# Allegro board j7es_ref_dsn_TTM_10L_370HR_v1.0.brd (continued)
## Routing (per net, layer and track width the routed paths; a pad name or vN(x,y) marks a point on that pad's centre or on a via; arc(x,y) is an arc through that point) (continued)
LPDDR4_CK_T: length 33.6
  TOP w0.229: U11.J8 v1(126.13,64.51) ; U11.P8 v1(126.13,68.41) ; v1(110.25,65.75) 110.25,65.75 U9.H1
  L2-SIGNAL w0.14: v1(126.13,68.41) 126.71,67.83 126.71,67.31 126.35,66.96 v1(126.35,66.56) 126.35,66.09 126.47,65.98 126.47,64.84 v1(126.13,64.51)
  L7-SIGNAL w0.163: v1(126.35,66.56) 126.35,66.03 125.92,65.6 121.7,65.6 120.99,64.89 120.15,64.89 119.99,64.72 119.99,64.06 119.99,63.78 119.62,63.41 119.24,63.41 118.97,63.41 118.59,63.79 118.59,64.81 118.46,64.94 118.07,64.94 117.86,64.72 117.86,64.08 117.86,63.81 117.43,63.38 117.05,63.38 116.78,63.38 116.46,63.7 116.46,64.75 116.31,64.89 116.06,64.89 115.87,64.71 115.87,64.03 115.88,63.75 115.51,63.39 115,63.39 114.72,63.39 114.4,63.71 114.4,64.78 114.21,64.96 113.93,64.96 113.72,64.75 113.72,63.89 113.3,63.47 112.59,63.47 112.24,63.81 112.24,65.58 112.08,65.75 v1(110.25,65.75)
LPDDR4_CKE0: length 33.4
  TOP w0.33: U11.P4 129.11,68.26 129.12,68.26 129.27,68.41 v1(129.33,68.41) ; U9.G3 v1(108.65,64.95) ; U11.J4 v1(129.33,64.51)
  L2-SIGNAL w0.142: v1(129.33,68.41) 129.3,68.41 128.92,68.03 128.92,67.59 128.68,67.35 128.68,66.83 v1(128.92,66.56) 128.92,64.87 129.29,64.51 v1(129.33,64.51)
  L9-SIGNAL w0.142: v1(128.92,66.56) 128.92,66.2 128.67,65.95 128.06,65.95 127.94,65.84 127.94,65.44 127.82,65.31 127.56,65.31 127.45,65.43 127.45,65.99 127.34,66.11 126.78,66.11 125.72,66.11 121.79,66.11 120.01,64.33 116.18,64.33 116.03,64.48 116.03,65.42 115.93,65.52 115.34,65.52 115.14,65.32 115.14,64.47 114.99,64.33 114.43,64.33 114.29,64.47 114.29,65.5 114.14,65.65 113.51,65.65 113.36,65.5 113.36,64.94 113.21,64.79 112.82,64.79 112.68,64.93 112.68,65.31 112.34,65.65 111.28,65.65 110.97,65.34 109.05,65.34 v1(108.65,64.95)
LPDDR4_CKE1: length 33.4
  TOP w0.33: U11.P5 128.13,68.08 v1(127.73,68.41) ; U9.J3 v1(108.65,66.55) ; U11.J5 v1(127.73,64.51)
  L2-SIGNAL w0.142: v1(127.73,68.41) 127.74,68.41 128.13,68.01 128.13,67.59 127.86,67.32 127.86,66.83 v1(128.13,66.56) 128.13,65.33 128.13,65.32 128.13,64.86 127.77,64.51 v1(127.73,64.51)
  L9-SIGNAL w0.142: v1(128.13,66.56) 126.95,66.56 126.52,67 121.46,67 120.61,66.14 117.47,66.14 117.32,65.99 117.32,65.67 117.47,65.52 119.84,65.52 119.96,65.39 119.96,65.12 119.75,64.91 116.89,64.91 116.66,65.14 116.66,65.99 116.5,66.15 109.05,66.15 v1(108.65,66.55)
LPDDR4_CSN0_0: length 28.4
  TOP w0.33: U11.H4 v1(128.53,64.51) ; U9.J5 v1(107.05,66.55)
  L9-SIGNAL w0.142: v1(128.53,64.51) 128.12,64.91 127.56,64.91 127.13,64.49 126.92,64.49 125.7,65.7 122.07,65.7 120.24,63.87 114.17,63.87 113.76,64.28 113.21,64.28 113.03,64.1 113.03,63.11 112.83,62.91 112.53,62.91 112.32,63.11 112.32,64.35 111.96,64.71 110.74,64.71 110.58,64.55 108.42,64.55 108.25,64.71 108.25,65.11 108.02,65.34 108.01,65.34 107.67,65.34 107.45,65.56 107.45,66.15 v1(107.05,66.55)
LPDDR4_CSN0_1: length 28.2
  TOP w0.33: U11.R4 v1(128.53,68.41) ; U9.K3 v1(108.65,67.35)
  L9-SIGNAL w0.142: v1(128.53,68.41) 128.12,68.81 128.12,69.87 128.12,69.88 128.12,70.65 127.87,70.9 127.4,70.9 126.42,69.92 124.86,69.92 124.85,69.92 120.9,69.92 120.55,69.56 120.55,68.62 120.19,68.27 119.63,68.27 119.28,68.62 119.28,69.59 119.1,69.76 117.02,69.76 116.76,69.51 116.76,67.68 116.54,67.45 114.78,67.45 114.49,67.75 109.06,67.75 v1(108.65,67.35)
LPDDR4_CSN1_0: length 28.4
  TOP w0.33: U11.H3 v1(129.33,63.86) ; v1(107.05,64.95) 106.65,65.35 U9.G5
  L9-SIGNAL w0.142: v1(129.33,63.86) 128.93,63.46 128.93,62.36 128.71,62.14 128.35,62.14 128.12,62.37 128.12,62.85 127.31,63.66 126.54,63.66 126.29,63.41 114.02,63.41 113.79,63.19 113.79,62.65 113.56,62.42 111.94,62.42 111.72,62.64 111.72,63.5 111.48,63.75 107.62,63.75 107.46,63.91 107.46,64.54 v1(107.05,64.95)
LPDDR4_CSN1_1: length 28.3
  TOP w0.33: U9.J2 109.05,66.94 v1(109.45,66.55) ; v1(130.13,69.06) 129.73,68.73 U11.R3
  L9-SIGNAL w0.142: v1(130.13,69.06) 129.72,69.47 129.72,69.54 129.73,69.54 129.73,70.01 129.57,70.17 129.08,70.17 128.93,70.02 128.93,67.6 128.93,67.6 128.93,67.59 128.69,67.36 128.69,67.36 128.66,67.34 127.82,67.34 126.68,68.48 126.68,69.25 126.47,69.46 121.4,69.46 121.06,69.11 121.06,68.05 119.95,66.94 109.85,66.94 v1(109.45,66.55)
LPDDR4_DM0_DBI0#: length 31.4
  TOP w0.33: v1(130.13,61.26) 130.13,61.26 U11.C3 ; U9.A3 v1(108.65,60.15)
  L4-SIGNAL w0.163: v1(130.13,61.26) 129.87,61 129.5,61 129.49,61 129.16,61 128.93,60.77 128.93,59.8 128.93,59.8 128.93,59.79 128.64,59.5 126.24,59.5 125.58,58.84 125.4,58.84 124.64,58.84 124.18,58.38 121.78,58.38 121.42,58.03 119.65,58.03 119.51,58.18 119.51,58.66 119.66,58.82 121.26,58.82 121.41,58.97 121.41,59.25 121.23,59.43 116.23,59.43 115.9,59.76 115.9,60.34 115.75,60.49 115.42,60.49 115.27,60.34 115.27,60.01 115.11,59.86 114.83,59.86 114.12,60.57 111.28,60.57 110.39,59.68 109.06,59.68 108.65,60.09 v1(108.65,60.15)
LPDDR4_DM1_DBI1#: length 25.5
  TOP w0.33: U11.C10 v1(124.53,60.61) ; U9.E4 v1(107.85,63.35)
  L2-SIGNAL w0.142: v1(124.53,60.61) 124.13,60.21 124.13,59.88 123.14,58.89 116.83,58.89 116.41,59.31 115.41,59.31 115.26,59.46 115.26,60.37 115.11,60.52 114.88,60.52 114.73,60.37 114.73,59.98 114.57,59.83 114.33,59.83 114.17,59.98 114.17,60.34 113.96,60.55 113.68,60.55 113.53,60.4 113.53,60.29 113.38,60.14 113.15,60.14 113,60.29 113,60.4 112.84,60.55 112.62,60.55 112.46,60.4 112.46,60.29 112.31,60.14 112.08,60.14 111.93,60.29 111.93,60.4 111.78,60.55 111.55,60.55 111.4,60.4 111.4,60.29 111.24,60.14 111.02,60.14 110.86,60.29 110.86,60.39 110.71,60.54 107.66,60.54 107.45,60.75 107.45,62.94 v1(107.85,63.35)
LPDDR4_DM2_DBI2#: length 31.5
  TOP w0.33: v1(130.13,71.66) 130.13,71.66 U11.Y3 ; v1(110.25,69.75) 110.25,69.75 U9.N1
  L4-SIGNAL w0.163: v1(110.25,69.75) 110.3,69.75 110.36,69.8 110.72,69.8 111.14,69.38 112.01,69.38 112.16,69.23 112.63,69.23 113.04,69.64 113.04,70.13 113.74,70.83 113.74,71.77 113.89,71.92 117.14,71.92 117.3,72.08 117.3,72.3 117.14,72.46 115.21,72.46 115.05,72.62 115.05,72.83 115.21,72.99 117.63,72.99 117.83,72.79 117.83,72.1 118.06,71.87 119.84,71.87 119.99,71.72 119.99,71.26 120,71.25 120,70.34 120.15,70.18 121.35,70.18 122.68,71.51 126.44,71.51 126.75,71.83 128.38,71.83 128.44,71.88 129.9,71.88 v1(130.13,71.66)
LPDDR4_DM3_DBI3#: length 22
  TOP w0.33: v1(123.73,72.31) 123.73,72.31 U11.Y10 ; v1(107.05,71.35) 107.05,71.35 U9.R5
  L2-SIGNAL w0.142: v1(123.73,72.31) 123.56,72.31 123.37,72.51 123.37,73.08 122.72,73.73 122.28,73.73 120.9,75.1 116.84,75.1 116.69,74.94 116.69,74.54 116.54,74.39 114.67,74.39 114.51,74.54 114.51,74.92 114.36,75.07 112.23,75.07 112.2,75.05 112.19,75.05 110.49,73.35 109.28,73.35 108.25,72.32 108.25,71.97 108.03,71.75 107.45,71.75 v1(107.05,71.35)
LPDDR4_DQ0: length 31.4
  TOP w0.33: v1(130.93,59.96) 130.88,59.96 130.55,60.28 U11.B2 ; U9.A5 v1(107.05,60.14)
  L4-SIGNAL w0.163: v1(107.05,60.14) 107.05,59.57 108.41,58.21 109.25,58.21 109.4,58.06 109.4,57.52 109.55,57.37 110.01,57.37 110.16,57.52 110.16,58.08 110.31,58.23 110.72,58.23 110.87,58.08 110.87,56.5 111.25,56.13 113.77,56.13 114.2,56.56 114.49,56.56 124.84,56.56 125.09,56.81 125.09,57.21 125.35,57.47 127.18,57.47 127.79,58.08 129.66,58.08 130.93,59.35 v1(130.93,59.96)
LPDDR4_DQ1: length 31.4
  TOP w0.33: U11.C2 v1(130.93,60.61) ; U9.A6 v1(106.25,60.14)
  L4-SIGNAL w0.163: v1(106.25,60.14) 106.44,59.96 106.44,59.49 110.26,55.67 114.03,55.67 114.45,56.1 127.45,56.1 128.17,56.82 128.17,56.84 128.95,57.62 129.84,57.62 131.37,59.15 131.37,60.17 v1(130.93,60.61)
LPDDR4_DQ2: length 31.4
  TOP w0.33: U11.E2 v1(130.93,61.91) ; U9.B5 v1(107.05,60.95)
  L4-SIGNAL w0.163: v1(130.93,61.91) 130.53,61.51 130.53,59.6 129.54,58.61 126.64,58.61 125.96,57.93 125.02,57.93 124.83,57.74 124.56,57.47 122.16,57.47 121.7,57.01 115.19,57.01 114.71,57.49 114.71,58.54 113.62,59.63 111.67,59.63 111.66,59.63 110.79,58.77 108.59,58.77 107.45,59.9 107.45,60.55 v1(107.05,60.95)
LPDDR4_DQ3: length 31.4
  TOP w0.33: U9.C2 v1(109.45,61.75) ; U11.F2 v1(130.93,63.21)
  L4-SIGNAL w0.163: v1(130.93,63.21) 131.15,63.21 131.32,63.04 131.32,62.46 131.18,62.31 130.94,62.31 130.34,62.92 130.34,63.23 130.22,63.35 129.88,63.35 129.77,63.24 129.77,62.89 129.49,62.61 129.28,62.61 128.54,61.87 127.8,61.87 127.09,62.58 126.72,62.58 126.26,63.03 120.07,63.03 119.52,63.58 118.7,63.58 118.49,63.78 117.78,63.78 117.62,63.93 117.62,64.4 117.47,64.55 117.24,64.55 117.09,64.4 117.09,63.93 116.94,63.78 116.55,63.78 116.39,63.93 116.39,64.48 116.24,64.63 116.01,64.63 115.86,64.48 115.86,63.93 115.71,63.78 115.48,63.78 115.33,63.93 115.33,64.48 115.17,64.63 114.94,64.63 114.79,64.48 114.79,63.93 114.64,63.78 111.97,63.78 111.48,63.29 111.48,62.56 111.32,62.4 110.77,62.4 110.52,62.15 109.86,62.15 v1(109.45,61.75)
LPDDR4_DQ4: length 31.4
  TOP w0.33: U9.B4 107.45,61.35 v1(107.85,60.95) ; U11.F4 129.33,63.21 v1(129.33,63.21)
  L4-SIGNAL w0.163: v1(107.85,60.95) 108.26,61.35 108.26,64.31 108.49,64.54 110.72,64.54 111.35,65.17 113.69,65.17 114.24,65.73 120.57,65.73 120.88,65.42 120.88,64.25 121.05,64.08 121.37,64.08 121.52,64.23 121.52,65.25 122.02,65.75 126.92,65.75 127.23,66.06 128.51,66.06 128.93,65.64 128.93,63.61 v1(129.33,63.21)
LPDDR4_DQ5: length 31.4
  TOP w0.33: U11.E4 v1(128.53,62.56) ; U9.C3 v1(108.65,61.75)
  L4-SIGNAL w0.163: v1(128.53,62.56) 128.4,62.56 128.13,62.83 128.13,65.46 127.91,65.67 127.35,65.67 126.95,65.28 126.95,63.86 126.48,63.39 122,63.39 121.82,63.57 120.45,63.57 120.29,63.72 120.29,65.12 120.14,65.27 119.65,65.27 119.5,65.12 119.5,64.22 119.35,64.07 118.97,64.07 118.83,64.21 118.82,64.22 118.82,65.04 118.6,65.27 114.63,65.27 114.07,64.71 114,64.71 111.65,64.71 110.68,63.74 109.29,63.74 109.05,63.51 109.05,62.15 v1(108.65,61.75)
LPDDR4_DQ6: length 31.5
  TOP w0.33: v1(128.53,60.61) 128.59,60.61 128.91,60.93 U11.C4 ; U9.A2 v1(109.45,60.15)
  L4-SIGNAL w0.163: v1(128.53,60.61) 127.78,59.86 126.92,59.86 126.77,60.01 126.77,60.47 126.62,60.62 125.89,60.62 125.73,60.46 125.73,59.81 125.73,59.8 125.73,59.79 125.49,59.56 125.48,59.56 125.41,59.49 125.21,59.49 124.43,59.49 124.23,59.49 124.03,59.69 124.03,60.47 123.9,60.59 123.52,60.59 123.37,60.44 123.37,59.25 123.22,59.1 122.63,59.1 122.48,59.24 122.48,59.66 122.21,59.93 119.6,59.93 119.45,60.09 119.45,60.31 119.6,60.47 121.21,60.47 121.36,60.62 121.36,60.85 121.21,61 119.07,61 118.92,60.85 118.92,60.09 118.77,59.93 116.51,59.93 116.36,60.09 116.36,60.87 116.2,61.03 111.09,61.03 110.61,60.54 109.85,60.54 v1(109.45,60.15)
LPDDR4_DQ7: length 31.4
  TOP w0.33: v1(129.33,60.61) 129.33,60.6 128.93,60.28 U11.B4 ; U9.A4 v1(107.85,60.14)
  L4-SIGNAL w0.163: v1(129.33,60.61) 129.61,60.32 129.61,60.32 129.73,60.2 129.73,59.66 129.24,59.17 126.55,59.17 125.77,58.38 125.21,58.38 124.83,58.38 124.37,57.93 121.97,57.93 121.61,57.57 117.01,57.57 116.84,57.74 116.84,58.11 117.02,58.28 118.82,58.28 118.97,58.44 118.97,58.82 118.82,58.97 114.96,58.97 113.82,60.11 111.47,60.11 110.58,59.22 108.78,59.22 v1(107.85,60.14)
LPDDR4_DQ8: length 25.5
  TOP w0.33: U11.B11 v1(122.93,59.96) ; U9.D1 109.85,62.95 v1(110.25,62.55)
  L2-SIGNAL w0.142: v1(122.93,59.96) 123.32,60.44 123.32,60.77 123.09,61 122.77,61 122.74,60.98 122.32,60.98 122.29,61 121.96,61 121.96,61 120.14,61 119.3,61 119.11,61.19 119.11,64.54 118.97,64.68 118.54,64.68 118.43,64.57 118.43,60.9 118.25,60.72 117.88,60.72 117.72,60.88 117.72,62.4 117.57,62.55 116.7,62.55 116.47,62.78 112.24,62.78 112.09,62.63 112.09,62.13 111.92,61.96 111.65,61.96 111.51,62.1 111.51,62.58 111.38,62.7 110.82,62.7 110.66,62.55 v1(110.25,62.55)
LPDDR4_DQ9: length 25.6
  TOP w0.33: U9.C4 v1(107.85,61.75) ; U11.C11 v1(122.93,60.61)
  L2-SIGNAL w0.142: v1(122.93,60.61) 122.23,59.91 120.79,59.91 120.64,60.06 120.64,60.39 120.48,60.54 120.26,60.54 120.1,60.39 120.1,60.06 119.95,59.91 119.72,59.91 119.57,60.06 119.57,60.39 119.42,60.54 119.19,60.54 119.04,60.39 119.04,60.06 118.91,59.93 117.48,59.93 117.26,60.15 117.26,61.41 117.07,61.6 116.85,61.6 116.37,61.12 116.05,61.12 115.85,61.32 115.85,62.2 115.72,62.32 114.88,62.32 114.71,62.14 114.71,61.66 114.55,61.51 114.34,61.51 114.19,61.66 114.19,62.09 114.03,62.24 113.82,62.24 113.65,62.08 113.65,61.63 113.5,61.48 113.27,61.48 113.12,61.63 113.12,62.14 112.95,62.31 112.74,62.31 112.59,62.15 112.59,61.65 112.43,61.49 111.06,61.49 110.65,61.91 110.65,61.91 110.42,62.14 110.41,62.14 110.41,62.15 109.29,62.15 109.06,62.38 109.06,62.39 109.05,62.39 109.05,62.74 108.85,62.94 108.49,62.94 108.26,62.71 108.26,62.38 108.26,62.38 108.26,62.15 v1(107.85,61.75)
LPDDR4_DQ10: length 25.5
  TOP w0.33: U11.E11 122.93,62.56 v1(122.93,62.56) ; U9.F1 v1(110.25,64.15)
  L2-SIGNAL w0.142: v1(110.25,64.15) 110.84,64.15 110.97,64.28 110.97,64.46 111.27,64.76 111.51,64.76 111.66,64.61 111.66,64.17 111.8,64.02 112.12,64.02 112.27,64.18 112.27,64.61 112.42,64.76 112.65,64.76 112.8,64.61 112.8,64.18 112.96,64.02 113.19,64.02 113.34,64.18 113.34,64.61 113.49,64.76 113.72,64.76 113.87,64.61 113.87,64.18 114.02,64.02 114.33,64.02 114.48,64.18 114.48,65.65 114.66,65.83 114.96,65.83 115.11,65.67 115.11,64.13 115.26,63.98 115.59,63.98 115.74,64.13 115.74,65.65 115.92,65.83 119.89,65.83 120.28,65.44 120.28,62.3 120.43,62.14 120.75,62.14 120.91,62.3 121.5,62.3 121.65,62.14 122.08,62.14 122.51,62.14 v1(122.93,62.56)
LPDDR4_DQ11: length 25.6
  TOP w0.33: U11.F11 v1(123.73,62.56) ; U9.G2 109.05,65.35 v1(109.45,64.95)
  L2-SIGNAL w0.142: v1(109.45,64.95) 109.85,64.55 110.42,64.55 111.09,65.22 113.85,65.22 114.01,65.37 114.01,65.6 113.85,65.75 111.46,65.75 111.3,65.9 111.3,66.13 111.45,66.28 112.96,66.28 113.32,66.64 114.09,66.64 114.44,66.28 120.07,66.28 120.74,65.61 120.74,62.88 120.87,62.75 121.58,62.75 121.84,63.01 123.09,63.01 123.26,62.84 123.45,62.84 v1(123.73,62.56)
LPDDR4_DQ12: length 25.5
  TOP w0.33: U9.F2 v1(109.45,64.15) ; U11.F9 v1(124.53,62.56)
  L2-SIGNAL w0.142: v1(109.45,64.15) 109.21,64.15 109.05,64.3 109.05,65.97 109.24,66.15 109.66,66.15 109.85,65.96 109.85,65.91 109.85,65.91 109.85,65.58 109.85,65.58 109.85,65.5 110.01,65.34 110.52,65.34 110.69,65.52 110.69,66.54 111.43,67.27 111.9,67.27 112.05,67.12 112.05,66.92 112.21,66.77 112.73,66.77 112.88,66.92 112.88,67.12 113.03,67.27 114.1,67.27 114.63,66.74 120.27,66.74 121.2,65.81 121.2,63.78 121.4,63.58 121.96,63.58 122.14,63.41 123.12,63.41 123.42,63.1 124.78,63.1 124.93,62.95 124.93,62.67 124.82,62.56 v1(124.53,62.56)
LPDDR4_DQ13: length 25.5
  TOP w0.33: U11.E9 v1(125.33,62.56) ; U9.F3 v1(108.65,64.15)
  L2-SIGNAL w0.142: v1(125.33,62.56) 125.53,62.56 125.76,62.78 125.76,63.23 125.55,63.44 123.57,63.44 123.22,63.79 122.28,63.79 121.65,64.42 121.65,66.03 120.46,67.22 114.82,67.22 114.31,67.73 111.2,67.73 110.42,66.95 108.46,66.95 108.25,66.74 108.25,64.54 v1(108.65,64.15)
LPDDR4_DQ14: length 25.6
  TOP w0.33: U9.D3 108.25,62.95 v1(108.65,62.55) ; v1(125.33,60.61) 125.33,60.61 124.93,60.93 U11.C9
  L2-SIGNAL w0.142: v1(108.65,62.55) 108.65,62.3 108.81,62.14 108.82,62.14 109.05,61.91 109.05,61.59 109.06,61.59 109.06,61.58 109.29,61.35 110.56,61.35 110.9,61.01 115.48,61.01 115.72,60.77 115.72,60.08 116.01,59.79 116.63,59.79 117.07,59.35 122.94,59.35 123.8,60.21 123.8,60.7 124.54,61.43 125.78,61.43 126.05,61.16 126.05,60.54 125.73,60.21 125.73,59.63 125.53,59.43 125.16,59.43 124.93,59.66 124.93,60.21 v1(125.33,60.61)
LPDDR4_DQ15: length 25.5
  TOP w0.33: U9.F5 v1(107.05,64.15) ; U11.B9 v1(124.53,59.96)
  L2-SIGNAL w0.142: v1(107.05,64.15) 106.65,63.75 106.65,59.96 106.93,59.68 113.63,59.68 114.46,58.85 116.23,58.85 116.64,58.44 123.33,58.44 123.42,58.53 124.43,58.53 124.74,58.84 124.74,59.17 124.53,59.38 v1(124.53,59.96)
LPDDR4_DQ16: length 31.6
  TOP w0.33: U9.L5 v1(107.05,68.15) ; U11.AA2 130.53,72.63 v1(130.13,72.96)
  L4-SIGNAL w0.163: v1(130.13,72.96) 130,73.09 129.41,73.09 129.08,73.41 127.55,73.41 127.36,73.61 127.36,73.91 127.35,73.95 127.23,74.07 126.86,74.07 126.71,73.91 126.71,73.22 126.53,73.04 125.89,73.04 125.73,73.2 125.73,74.24 125.5,74.46 112.96,74.46 112.06,73.57 112.06,72.11 111.7,71.75 109.28,71.75 109.05,71.53 109.05,71.16 108.84,70.95 108.47,70.95 108.25,70.73 108.25,70.36 108.04,70.15 107.65,70.15 107.45,69.95 107.45,68.55 v1(107.05,68.15)
LPDDR4_DQ17: length 31.5
  TOP w0.33: U11.Y2 130.93,72.31 v1(130.93,72.31) ; U9.M5 106.65,69.35 v1(107.05,68.95)
  L4-SIGNAL w0.163: v1(107.05,68.95) 106.65,69.35 106.65,70.58 106.65,70.58 106.65,70.71 106.89,70.94 107.02,70.94 107.03,70.95 107.24,70.95 107.45,71.16 107.45,71.53 107.67,71.75 108.04,71.75 108.25,71.97 108.25,72.31 108.95,73.01 110.2,73.01 112.6,75.4 128.88,75.4 130.93,73.35 v1(130.93,72.31)
LPDDR4_DQ18: length 31.6
  TOP w0.33: U9.N5 v1(107.05,69.75) ; U11.V2 130.71,70.86 130.72,70.86 130.87,71.01 v1(130.93,71.01)
  L4-SIGNAL w0.163: v1(130.93,71.01) 130.53,71.41 130.53,73.17 130.27,73.42 129.56,73.42 129.33,73.66 129.33,74.29 128.68,74.95 128.07,74.95 127.82,74.7 126.6,74.7 126.35,74.95 112.79,74.95 111.53,73.69 111.53,72.91 111.17,72.55 109.29,72.55 109.05,72.32 109.05,71.96 108.84,71.75 108.49,71.75 108.25,71.52 108.25,71.19 108.25,71.18 108.02,70.95 107.69,70.95 107.45,70.71 107.45,70.35 107.05,69.95 v1(107.05,69.75)
LPDDR4_DQ19: length 31.6
  TOP w0.33: U9.L4 v1(107.85,68.15) ; U11.U2 v1(130.13,69.71)
  L4-SIGNAL w0.163: v1(130.13,69.71) 130.11,69.71 129.54,70.28 129.11,70.28 128.93,70.1 128.93,67.23 128.67,66.97 127.51,66.97 126.69,66.16 120.99,66.16 120.84,66.31 120.84,67.11 120.69,67.26 120.14,67.26 119.99,67.11 119.99,66.39 119.79,66.19 114.06,66.19 113.56,65.69 110.99,65.69 110.64,65.35 108.49,65.35 108.26,65.58 108.26,65.62 108.25,65.62 108.25,67.75 v1(107.85,68.15)
LPDDR4_DQ20: length 31.5
  TOP w0.33: U9.L2 v1(109.45,68.15) ; U11.U4 v1(128.53,69.71)
  L4-SIGNAL w0.163: v1(128.53,69.71) 128.13,69.31 128.13,67.56 127.9,67.34 127.21,67.34 126.83,66.96 122.82,66.96 122.82,66.96 121.66,66.96 120.77,67.86 119.29,67.86 118.97,67.54 118.97,67.07 118.82,66.91 118.59,66.91 118.44,67.07 118.44,67.45 118.29,67.6 118.06,67.6 117.91,67.45 117.91,66.8 117.75,66.65 117.53,66.65 117.37,66.8 117.37,67.45 117.22,67.6 116.99,67.6 116.84,67.45 116.84,66.8 116.69,66.65 116.46,66.65 116.31,66.8 116.31,67.45 116.15,67.6 115.93,67.6 115.77,67.45 115.77,66.8 115.62,66.65 115.39,66.65 115.24,66.8 115.24,67.45 115.09,67.6 114.81,67.6 113.35,66.15 109.29,66.15 109.06,66.38 109.06,67.75 v1(109.45,68.15)
LPDDR4_DQ21: length 31.6
  TOP w0.33: v1(128.53,70.36) 128.53,70.36 U11.V4 ; U9.L1 v1(110.25,68.15)
  L4-SIGNAL w0.163: v1(128.53,70.36) 128.52,70.36 128.2,70.69 128.2,70.69 128.03,70.86 127.43,70.86 127.23,70.66 127.23,69.75 126.98,69.5 126.98,68.19 126.07,67.28 122.02,67.28 120.98,68.32 119.46,68.32 119.29,68.48 119.29,68.82 119.14,68.97 118.54,68.97 118.4,68.84 118.4,68.42 118.13,68.16 117.89,68.16 117.35,68.7 115.01,68.7 114.81,68.9 114.81,69.18 114.96,69.33 116.41,69.33 116.56,69.48 116.56,69.79 116.36,69.99 114.66,69.99 114.2,69.54 114.2,67.66 113.23,66.69 111.63,66.69 110.25,68.07 v1(110.25,68.15)
LPDDR4_DQ22: length 31.6
  TOP w0.33: U11.Y4 128.93,71.98 v1(128.53,72.31) ; U9.N2 v1(109.45,69.75)
  L4-SIGNAL w0.163: v1(128.53,72.31) 128.12,72.72 127.18,72.72 126.36,71.9 124.71,71.9 123.14,73.47 122.05,73.47 121.79,73.22 121.79,72.8 121.67,72.67 121.67,72.38 121.51,72.23 121.09,72.23 120.94,72.08 120.94,71.85 121.09,71.69 121.51,71.69 121.67,71.54 121.67,71.15 121.3,70.78 120.61,70.78 120.46,70.93 120.46,72.09 120.22,72.33 118.44,72.33 118.29,72.48 118.29,73.29 118.14,73.45 114.63,73.45 114.48,73.29 114.48,72.65 114.33,72.5 114.11,72.5 113.94,72.66 113.94,73.29 113.79,73.45 113.44,73.45 113.28,73.29 113.28,71.15 112.03,69.89 111.28,69.89 110.91,70.26 110.53,70.26 110.42,70.15 110.41,70.15 110.41,70.14 110.09,70.14 110.09,70.14 109.85,70.14 v1(109.45,69.75)
LPDDR4_DQ23: length 31.6
  TOP w0.33: U9.N4 v1(107.85,69.75) ; U11.AA4 129.33,72.31 v1(129.33,72.31)
  L4-SIGNAL w0.163: v1(129.33,72.31) 129.33,72.73 128.98,73.07 127.02,73.07 126.65,72.71 125.49,72.71 124.83,73.37 123.9,73.37 123.37,73.9 119.79,73.9 119.64,73.75 119.64,73.54 119.81,73.37 121.18,73.37 121.33,73.22 121.33,72.99 121.18,72.84 118.93,72.84 118.78,72.99 118.78,73.75 118.63,73.9 113.08,73.9 112.74,73.56 112.74,72.05 111.63,70.95 109.29,70.95 109.05,70.71 109.05,70.37 108.84,70.16 108.83,70.16 108.82,70.15 108.49,70.15 108.48,70.16 108.47,70.16 108.06,69.75 v1(107.85,69.75)
LPDDR4_DQ24: length 22.1
  TOP w0.33: v1(122.93,72.96) 123.33,72.63 U11.AA11 ; v1(108.65,72.15) 108.65,72.15 U9.T3
  L2-SIGNAL w0.142: v1(122.93,72.96) 122.62,73.27 122.07,73.27 120.8,74.54 118.67,74.54 118.52,74.39 118.52,73.75 118.36,73.6 118.02,73.6 117.89,73.73 117.89,74.44 117.69,74.64 117.42,74.64 117.26,74.47 117.26,73.25 117.09,73.08 116.88,73.08 116.72,73.24 116.72,73.78 116.57,73.93 114.02,73.93 113.87,74.08 113.87,74.46 113.71,74.61 113.49,74.61 113.33,74.46 113.33,74.22 113.18,74.07 112.95,74.07 112.8,74.22 112.8,74.46 112.65,74.61 112.42,74.61 112.27,74.46 112.27,74.22 112.09,74.04 111.88,74.04 110.92,73.08 110.92,73.07 110.79,72.94 110.35,72.94 110.35,72.94 109.44,72.94 v1(108.65,72.15)
LPDDR4_DQ25: length 22.1
  TOP w0.33: v1(109.45,72.15) 109.06,72.54 U9.T2 ; v1(122.93,72.31) 122.93,72.31 U11.Y11
  L2-SIGNAL w0.142: v1(122.93,72.31) 122.53,72.71 121.96,72.71 121.73,72.47 121.73,72.47 121.64,72.38 121.41,72.38 121.25,72.54 121.25,73.41 120.74,73.92 120.47,73.92 120.32,73.77 120.32,72.71 120.17,72.56 119.81,72.56 119.66,72.71 119.66,73.88 119.48,74.06 119.13,74.06 118.97,73.9 118.97,72.74 118.82,72.58 118.48,72.58 118.33,72.74 118.33,72.93 118.17,73.08 117.94,73.08 117.79,72.93 117.79,72.74 117.64,72.58 116.46,72.58 115.65,73.4 111.89,73.4 111.38,72.89 111.38,72.38 111.12,72.12 110.9,72.12 110.46,72.56 109.68,72.56 109.45,72.33 v1(109.45,72.15)
LPDDR4_DQ26: length 22.1
  TOP w0.33: U11.V11 123.33,70.68 v1(122.93,70.36) ; v1(109.45,70.55) 109.06,70.94 U9.P2
  L2-SIGNAL w0.142: v1(109.45,70.55) 109.85,70.15 110.56,70.15 110.9,69.81 111.15,69.81 111.3,69.97 111.3,70.32 111.46,70.47 111.68,70.47 111.84,70.32 111.84,69.87 111.99,69.71 112.29,69.71 112.42,69.84 112.42,70.63 112.57,70.78 112.83,70.78 113,70.6 113,69.87 113.16,69.71 114.91,69.71 115.32,70.12 115.8,70.12 116.2,69.71 116.76,69.71 116.92,69.87 116.92,70.78 117.08,70.94 117.53,70.94 117.67,70.81 117.67,69.99 117.82,69.84 118.14,69.84 118.31,70.02 118.31,70.75 118.47,70.91 119.58,70.91 119.89,70.6 119.89,70.17 120.04,70.02 121.23,70.02 121.62,70.4 121.62,70.55 121.82,70.76 122.53,70.76 v1(122.93,70.36)
LPDDR4_DQ27: length 22
  TOP w0.33: U11.U11 123.33,70.03 v1(123.73,70.36) ; U9.P3 v1(108.65,70.55)
  L2-SIGNAL w0.142: v1(108.65,70.55) 109.06,70.14 109.06,69.58 109.29,69.35 111.71,69.35 111.8,69.26 117.04,69.26 117.17,69.38 118.11,69.38 118.27,69.22 118.27,68.72 118.43,68.57 118.72,68.57 118.85,68.7 118.85,70.27 118.98,70.4 119.28,70.4 119.43,70.25 119.43,69.69 119.58,69.54 120.5,69.54 120.65,69.38 120.65,68.79 120.8,68.63 121.12,68.63 121.28,68.79 121.28,69.41 121.71,69.84 122.15,69.84 122.16,69.84 123.5,69.84 123.73,70.06 v1(123.73,70.36)
LPDDR4_DQ28: length 22.1
  TOP w0.33: U9.P5 106.65,70.95 v1(107.05,70.55) ; v1(124.53,70.36) 124.53,70.36 124.67,70.21 124.75,70.21 U11.U9
  L2-SIGNAL w0.142: v1(107.05,70.55) 107.27,70.55 107.68,70.14 107.69,70.14 107.69,70.14 108.02,70.14 108.02,70.14 108.03,70.14 108.25,69.92 108.25,69.91 108.25,69.91 108.25,69.58 108.49,69.34 108.82,69.34 108.82,69.34 108.83,69.34 109.05,69.12 109.05,69.11 109.05,69.11 109.05,68.78 109.05,68.78 109.05,68.77 109.27,68.54 110.49,68.54 110.67,68.72 117.58,68.72 118.19,68.11 121.56,68.11 121.73,68.28 121.73,69.22 121.96,69.46 121.97,69.46 121.97,69.46 124.38,69.46 124.53,69.6 v1(124.53,70.36)
LPDDR4_DQ29: length 22
  TOP w0.33: U11.V9 124.93,70.68 v1(125.33,71.01) ; U9.R4 107.85,71.35 v1(107.85,71.35)
  L2-SIGNAL w0.142: v1(125.33,71.01) 125.71,71.01 125.93,71.24 125.93,71.67 125.68,71.92 125.5,71.92 125.49,71.91 125.16,71.91 125.15,71.92 123.9,71.92 123.89,71.91 123.56,71.91 123.55,71.92 122.3,71.92 122.29,71.91 121.96,71.91 121.96,71.92 120.63,71.92 120.46,72.09 116.22,72.09 115.38,72.93 112.08,72.93 111.86,72.71 111.86,71.9 111.63,71.66 110.71,71.66 110.63,71.75 108.49,71.75 108.09,71.35 v1(107.85,71.35)
LPDDR4_DQ30: length 22
  TOP w0.33: U11.Y9 125.33,72.31 v1(125.33,72.31) ; v1(107.85,72.15) 107.45,72.55 U9.T4
  L2-SIGNAL w0.142: v1(107.85,72.15) 107.85,72.29 109.05,73.49 109.05,73.92 109.29,74.15 110.65,74.15 112,75.5 112.01,75.5 112.04,75.53 114.63,75.53 115.09,75.07 116,75.07 116.51,75.58 121.07,75.58 121.14,75.5 122.47,74.18 122.66,74.18 124.53,72.31 v1(125.33,72.31)
LPDDR4_DQ31: length 22
  TOP w0.33: U9.T5 106.65,72.55 v1(107.05,72.15) ; U11.AA9 124.93,72.63 v1(124.53,72.96)
  L2-SIGNAL w0.142: v1(124.53,72.96) 124.34,72.96 121.6,75.69 121.21,76.09 111.79,76.09 110.64,74.95 109.29,74.95 109.25,74.95 109.05,74.75 109.05,74.36 108.83,74.14 108.82,74.14 108.82,74.15 108.49,74.15 108.26,73.91 108.26,73.91 108.25,73.9 108.25,73.35 v1(107.05,72.15)
LPDDR4_DQS0_N: length 31.4
  TOP w0.229: v1(130.13,61.91) 130.13,61.91 U11.E3 ; v1(110.25,60.95) 110.25,60.95 U9.B1
  L4-SIGNAL w0.163: v1(130.13,61.91) 129.94,61.91 129.51,61.48 129.13,61.48 128.8,61.15 122.16,61.15 121.2,62.12 120.35,62.12 119.71,61.48 119.12,61.48 118.67,61.93 118.67,62.59 118.48,62.78 118.2,62.78 118.06,62.64 118.06,60.81 117.74,60.49 117.47,60.49 117.25,60.49 116.89,60.85 116.89,62.65 116.64,62.91 116.21,62.91 116,62.69 116,62.39 115.73,62.12 115.1,62.12 114.76,62.46 114.76,62.74 114.59,62.91 114.34,62.91 114.15,62.72 114.15,61.89 113.77,61.51 113.49,61.51 113.21,61.51 112.83,61.89 112.83,62.81 112.76,62.88 112.46,62.88 112.29,62.72 112.29,61.8 111.92,61.43 111.01,61.43 110.6,61.02 110.56,61.02 110.56,61.02 110.33,61.02 v1(110.25,60.95)
LPDDR4_DQS0_P: length 31.4
  TOP w0.229: U11.D3 v1(129.33,61.91) ; v1(109.45,60.95) 109.05,61.35 U9.B2
  L4-SIGNAL w0.163: v1(129.33,61.91) 129.24,61.81 129,61.81 128.67,61.48 122.3,61.48 121.34,62.45 120.21,62.45 119.57,61.81 119.25,61.81 119,62.07 119,62.73 118.62,63.11 118.06,63.11 117.73,62.78 117.73,60.95 117.6,60.82 117.38,60.82 117.22,60.99 117.22,62.79 116.77,63.24 116.08,63.24 115.67,62.83 115.67,62.56 115.57,62.45 115.23,62.45 115.09,62.6 115.09,62.88 114.73,63.24 114.2,63.24 113.82,62.85 113.82,62.03 113.63,61.84 113.34,61.84 113.16,62.03 113.16,62.95 112.89,63.21 112.32,63.21 111.96,62.85 111.96,61.94 111.79,61.76 110.87,61.76 110.46,61.35 110.42,61.35 110.42,61.35 110.1,61.35 110.1,61.34 110.05,61.34 109.65,60.95 v1(109.45,60.95)
LPDDR4_DQS1_N: length 25.5
  TOP w0.229: U11.E10 124.53,61.91 v1(124.53,61.91) ; U9.E2 v1(109.45,63.35)
  L2-SIGNAL w0.14: v1(109.45,63.35) 109.87,62.93 110.39,62.93 110.72,63.26 116.19,63.26 116.47,63.55 116.47,64.96 116.6,65.09 116.81,65.09 116.92,64.99 116.92,63.27 117.22,62.97 117.69,62.97 117.98,63.26 117.98,64.9 118.2,65.12 119.38,65.12 119.56,64.94 119.56,61.75 119.86,61.45 122.43,61.45 122.63,61.24 123.72,61.24 124.38,61.91 v1(124.53,61.91)
LPDDR4_DQS1_P: length 25.5
  TOP w0.229: U11.D10 123.73,61.91 v1(123.73,61.91) ; U9.E3 v1(108.65,63.35)
  L2-SIGNAL w0.14: v1(108.65,63.35) 109.05,63.75 110.44,63.75 110.64,63.54 116.07,63.54 116.19,63.66 116.19,65.08 116.48,65.37 116.93,65.37 117.2,65.1 117.2,63.39 117.34,63.25 117.57,63.25 117.7,63.38 117.7,64.78 117.7,65.01 118.08,65.39 119.5,65.39 119.84,65.05 119.84,61.86 119.98,61.72 122.54,61.72 122.75,61.52 123.6,61.52 123.73,61.65 v1(123.73,61.91)
LPDDR4_DQS2_N: length 31.5
  TOP w0.229: U11.V3 129.73,70.68 v1(130.13,71.01) ; U9.M2 v1(109.45,68.95)
  L4-SIGNAL w0.163: v1(130.13,71.01) 129.73,70.62 129.5,70.62 129.49,70.61 129.16,70.61 129.16,70.62 129.06,70.62 128.51,71.16 127.16,71.16 126.88,70.88 126.88,70.26 126.88,69.99 126.4,69.51 121.91,69.51 121.75,69.36 119.62,69.36 119.1,69.88 119.1,70.15 119.1,70.85 118.91,71.03 118.53,71.03 118.36,70.87 118.36,69.6 118.04,69.28 117.77,69.28 117.77,69.28 117.35,69.28 117.04,69.59 117.04,69.86 117.04,70.87 116.86,71.06 115.15,71.06 113.79,69.7 113.79,67.98 112.99,67.17 112,67.17 111.43,67.75 111.43,68.51 111.27,68.67 110.55,68.67 110.43,68.54 110.09,68.54 110.08,68.54 109.86,68.54 v1(109.45,68.95)
LPDDR4_DQS2_P: length 31.5
  TOP w0.229: U9.M3 v1(108.65,68.95) ; U11.W3 129.33,71.01 v1(129.33,71.01)
  L4-SIGNAL w0.163: v1(129.33,71.01) 129.13,71.01 128.65,71.49 127.03,71.49 126.55,71.01 126.55,70.12 126.26,69.84 121.77,69.84 121.62,69.69 119.76,69.69 119.43,70.02 119.43,70.98 119.05,71.36 118.39,71.36 118.03,71.01 118.03,69.74 117.91,69.61 117.49,69.61 117.37,69.73 117.37,71.01 116.99,71.39 115.01,71.39 113.46,69.84 113.46,68.11 112.85,67.5 112.14,67.5 111.76,67.88 111.76,68.65 111.4,69 110.76,69 110.42,69.34 108.9,69.34 108.65,69.09 v1(108.65,68.95)
LPDDR4_DQS3_N: length 22
  TOP w0.229: U11.V10 124.13,70.68 v1(124.53,71.01) ; v1(110.25,71.35) 110.25,71.35 U9.R1
  L2-SIGNAL w0.14: v1(110.25,71.35) 110.25,71.33 110.34,71.24 112.03,71.24 112.32,71.53 112.32,72.18 112.67,72.53 113.17,72.53 113.4,72.53 113.79,72.14 113.79,71.79 113.79,70.65 113.93,70.51 114.13,70.51 114.27,70.65 114.27,72.22 114.58,72.52 115.09,72.52 115.42,72.19 115.42,71.66 115.42,71.62 115.73,71.31 116.33,71.31 116.68,71.67 120.19,71.67 120.43,71.43 120.43,70.98 120.61,70.81 120.85,70.81 121.48,71.44 122.37,71.44 122.61,71.68 123.46,71.68 123.73,71.4 123.89,71.4 124.28,71.01 v1(124.53,71.01)
LPDDR4_DQS3_P: length 22
  TOP w0.229: U9.R2 109.05,71.75 v1(109.45,71.35) ; v1(123.73,71.01) 123.73,71.01 U11.W10
  L2-SIGNAL w0.14: v1(123.73,71.01) 123.34,71.4 122.73,71.4 122.49,71.16 121.6,71.16 120.96,70.53 120.49,70.53 120.15,70.87 120.15,71.31 120.08,71.39 116.8,71.39 116.44,71.03 115.61,71.03 115.14,71.51 115.14,71.66 115.14,72.08 114.97,72.24 114.69,72.24 114.55,72.1 114.55,70.53 114.25,70.23 113.82,70.23 113.51,70.54 113.51,71.91 113.51,72.02 113.28,72.25 112.79,72.25 112.6,72.06 112.6,71.41 112.14,70.96 109.85,70.96 v1(109.45,71.35)
LPDDR4_ODT_CA_A: length 9.9
  TOP w0.191: U11.G2 v1(130.93,63.86)
  L2-SIGNAL w0.102: v1(130.93,63.86) 131.32,63.47 131.32,62.4 131.6,62.12 135.62,62.12 v1(137.26,63.76)
  BOTTOM w0.191: R239.2 137.26,62.96 137.25,62.97 137.25,63.48 137.26,63.49 v1(137.26,63.76)
LPDDR4_ODT_CA_B: length 7.3
  TOP w0.191: U11.T2 v1(130.93,69.71)
  L2-SIGNAL w0.102: v1(136.09,69.75) 135.47,70.37 131.59,70.37 v1(130.93,69.71)
  BOTTOM w0.191: v1(136.09,69.75) R227.1
LPDDR4_RST#: length 22.6
  TOP w0.191: U11.T11 123.33,69.38 v1(122.93,69.06) ; U9.K6 v1(106.25,67.35)
  L2-SIGNAL w0.102: v1(106.25,67.35) 106.68,67.78 110.49,67.78 110.89,68.19 114.53,68.19 115.04,67.68 116.97,67.68 v1(117.35,68.06) 117.73,67.68 121.34,67.68 121.63,67.39 122.28,67.39 122.28,67.39 122.29,67.39 122.49,67.59 122.49,67.6 122.5,67.61 122.5,68.63 v1(122.93,69.06)
  BOTTOM w0.191: R228.1 R232.2 118.15,68.41 117.81,68.06 v1(117.35,68.06)
LPDDR4_ZQ0: length 1.8
  TOP w0.191: U11.A5 v1(128.53,59.96)
  BOTTOM w0.191: 127.89,59.2 R242.2 127.89,59.75 128.09,59.96 v1(128.53,59.96)
LPDDR4_ZQ1: length 1.7
  TOP w0.191: U11.A8 v1(126.13,59.96)
  BOTTOM w0.191: 126.75,59.2 R243.2 126.75,59.63 126.42,59.96 v1(126.13,59.96)
LS2_CT: length 1.5
  TOP w0.229: U6.6 156.11,109.82 155.7,110.23 155.62,110.23 C89.1
LS3_CT: length 1.5
  BOTTOM w0.229: C204.1 U22.6
MCAN0_RX: length 41.9
  TOP w0.191: U9.W5 107.05,75.34 v1(107.05,75.35)
  L7-SIGNAL w0.097: v1(107.05,75.35) 107.42,74.98 112.46,74.98 114.35,76.88 118.16,76.88 120.18,78.9 129.97,78.9 130.69,78.18 138.09,78.18 141.92,74.35 144.2,74.35 144.26,74.41 TPX270.1
MCAN0_TX: length 58.3
  TOP w0.191: v1(106.25,75.35) 105.85,74.95 U9.W6
  L9-SIGNAL w0.097: TPX293.1 155.96,73.27 141.86,73.27 137.41,77.71 131.7,77.71 130.17,79.24 117.73,79.24 112.67,74.18 109.45,74.18 109.45,74.18 108.5,74.18 108.29,74.4 108.29,74.4 108.22,74.47 108.22,74.7 107.95,74.97 106.63,74.97 v1(106.25,75.35)
MCAN2_RX/MLB0_MLBSIG: length 43.9
  TOP w0.191: v1(109.45,78.55) 109.45,78.54 U9.AC2
  L7-SIGNAL w0.097: v1(109.45,78.55) 109.89,78.98 110.4,78.98 112.52,81.1 138.22,81.1 142.11,77.21 148.84,77.21 TPX222.1
MCAN2_TX/MLB_INT#: length 39.7
  TOP w0.191: U9.AB1 110.25,77.74 v1(110.25,77.75)
  L5-PWR/GND w0.097: TPX357.1 145.41,76.82 142.24,76.82 137.84,81.22 122.13,81.22 120.32,79.41 117.27,79.41 115.95,78.09 110.98,78.09 110.63,77.75 v1(110.25,77.75)
MCASP0_ACLKX/SPI3_CS1: length 38.5
  TOP w0.191: U9.AB26 v1(89.45,77.75)
  L7-SIGNAL w0.097: TPX157.1 69.22,78.86 69.45,79.09 74.78,79.09 75.82,80.13 85.34,80.13 85.75,79.72 88.89,79.72 89.08,79.52 89.08,78.11 v1(89.45,77.75)
MCASP0_AFSX/SPI3_CS2: length 39.1
  TOP w0.191: U9.AB25 90.65,77.35 v1(90.25,77.75)
  L5-PWR/GND w0.097: v1(90.25,77.75) 90.13,77.75 89.74,78.15 86.54,78.15 86.03,77.64 56.59,77.64 56.01,78.22 53.21,78.22 TPX130.1
MCASP0_AXR0/PRG0_RGMII1_RD0: length 35.8
  TOP w0.191: v1(87.85,80.95) 88.25,80.55 U9.AF28
  L4-SIGNAL w0.097: v1(87.85,80.95) 87.48,81.32 86.44,81.32 84.11,83.65 54.13,83.65 TPX54.1
MCASP0_AXR1/PRG0_RGMII1_RD1: length 40.2
  TOP w0.191: v1(87.85,80.15) 88.25,79.75 U9.AE28
  L9-SIGNAL w0.097: v1(87.85,80.15) 87.41,80.58 86.49,80.58 86.41,80.51 54.02,80.51 54.01,80.52 49.65,80.52 TPX5.1
MCASP0_AXR2/PRG0_RGMII1_RX_CTL: length 37.9
  TOP w0.191: v1(90.25,79.35) 90.65,78.95 U9.AD25
  L9-SIGNAL w0.097: TPX55.1 55.75,80.13 56.79,79.09 77.7,79.09 78.4,79.78 89.81,79.78 v1(90.25,79.35)
MCASP0_AXR3: length 39.5
  TOP w0.191: U9.AC29 87.45,78.15 v1(87.05,78.55)
  L7-SIGNAL w0.097: v1(87.05,78.55) 86.18,78.55 85.58,77.94 55.52,77.94 55.24,78.22 49.4,78.22 TPX183.1
MCASP0_AXR4/PRG0_RGMII1_RXC: length 41.1
  TOP w0.191: U9.AE26 v1(89.45,80.15)
  L9-SIGNAL w0.097: v1(89.45,80.15) 89.02,80.58 89.02,80.77 89.01,80.77 89.01,81.1 88.8,81.32 88.47,81.32 88.2,81.59 88.21,81.6 88.21,81.9 88,82.11 87.67,82.11 87.67,82.12 86.15,82.12 85.6,82.67 74.8,82.67 73.66,81.52 55.23,81.52 54.68,80.97 51.73,80.97 TPX29.1
MCASP0_AXR5/MCAN9_TX: length 41.9
  TOP w0.191: U9.AC28 88.25,78.15 v1(87.85,78.55)
  BOTTOM w0.127: v1(87.85,78.55) 87.45,78.16 83.96,78.16 82.73,76.93 54.15,76.93 54.12,76.96 48.15,76.96 TPX158.1
MCASP0_AXR6/MCAN9_RX: length 37.8
  TOP w0.191: U9.AC27 89.05,78.15 v1(88.65,78.55)
  L7-SIGNAL w0.097: TPX132.1 52.97,78.47 69.71,78.47 70,78.75 75.08,78.75 75.44,79.11 77.72,79.11 78.36,79.75 85.09,79.75 85.9,78.93 88.27,78.93 v1(88.65,78.55)
MCASP0_AXR7/PRG0_RGMII1_TD0: length 42
  TOP w0.191: U9.AJ28 88.25,82.95 v1(87.85,83.35)
  L4-SIGNAL w0.097: v1(87.85,83.35) 87.85,84.23 85.09,86.98 49.53,86.98 TPX28.1
MCASP0_AXR8/PRG0_RGMII1_TD1: length 39.7
  TOP w0.191: U9.AH27 89.05,82.15 v1(88.65,82.55)
  L4-SIGNAL w0.097: TPX100.1 53.12,87.21 85.5,87.21 88.29,84.42 88.29,82.91 v1(88.65,82.55)
MCASP0_AXR9/PRG0_RGMII1_TD2: length 41.2
  TOP w0.191: v1(87.05,82.55) 87.45,82.15 U9.AH29
  L4-SIGNAL w0.097: TPX76.1 48.01,84.7 55.37,84.7 55.6,84.47 84.56,84.47 86.48,82.55 v1(87.05,82.55)
MCASP0_AXR10/PRG0_RGMII1_TD3: length 43.6
  TOP w0.191: U9.AG28 88.25,81.35 v1(87.85,81.75)
  L4-SIGNAL w0.097: TPX53.1 46.99,84.44 54.48,84.44 54.79,84.14 84.38,84.14 86.39,82.13 87.46,82.13 v1(87.85,81.75)
MCASP0_AXR11/PRG0_RGMII1_TX_CTL: length 43
  TOP w0.191: v1(88.65,81.75) 89.05,81.35 U9.AG27
  L4-SIGNAL w0.097: TPX75.1 52.07,88.25 55.37,88.25 56.01,87.62 85.72,87.62 89.05,84.29 89.05,82.15 v1(88.65,81.75)
MCASP0_AXR12/PRG0_RGMII1_TXC: length 41.1
  TOP w0.191: U9.AH28 88.25,82.15 v1(87.85,82.55)
  L4-SIGNAL w0.097: v1(87.85,82.55) 87.45,82.95 86.72,82.95 84.96,84.7 56.77,84.7 55.84,85.63 49.19,85.63 TPX4.1
MCASP0_AXR13/PRG0_PWM0_B2: length 42.2
  TOP w0.191: U9.AB24 v1(91.05,77.75)
  L5-PWR/GND w0.097: v1(91.05,77.75) 90.63,77.33 86.69,77.33 86.44,77.08 50.8,77.08 TPX110.1
MCASP1_ACLKX: length 36
  TOP w0.191: v1(88.65,77.75) 89.05,77.35 U9.AB27
  L9-SIGNAL w0.097: TPX83.1 58.04,76.32 58.8,77.08 85.98,77.08 86.28,77.38 88.28,77.38 v1(88.65,77.75)
MCASP1_AFSX/MCAN11_RX: length 43
  TOP w0.191: v1(87.85,76.95) 88.25,76.55 U9.AA28
  BOTTOM w0.127: v1(87.85,76.95) 87.45,76.56 83.68,76.56 83.57,76.44 58.04,76.44 57.29,75.69 46.88,75.69 TPX82.1
MCASP1_AXR0/PRG0_RGMII2_RD0: length 41.7
  TOP w0.191: U9.AE29 v1(87.05,80.15)
  L4-SIGNAL w0.097: v1(87.05,80.15) 86.01,80.15 85.55,80.6 81.06,80.6 78.58,83.08 48.35,83.08 TPX129.1
MCASP1_AXR1/PRG0_RGMII2_RD1: length 35.9
  TOP w0.191: v1(87.85,79.35) 88.25,78.95 U9.AD28
  L4-SIGNAL w0.097: v1(87.85,79.35) 87.45,79.75 86.1,79.75 85.46,80.38 78.49,80.38 77.75,81.11 72.83,81.11 71.28,82.67 TPX179.1
MCASP1_AXR2/PRG0_RGMII2_RX_CTL: length 36.4
  TOP w0.191: U9.AD29 87.45,78.95 v1(87.05,79.35)
  L4-SIGNAL w0.097: v1(87.05,79.35) 85.87,79.35 85.22,80 78.23,80 77.34,80.89 70.36,80.89 69.09,82.16 53.09,82.16 TPX104.1
MCASP1_AXR3/PRG0_RGMII2_RXC: length 45.5
  TOP w0.191: v1(89.45,78.55) 89.85,78.15 U9.AC26
  L4-SIGNAL w0.097: v1(89.45,78.55) 89.04,78.96 85.75,78.96 84.96,79.75 77.98,79.75 77.16,80.56 68.52,80.56 67.18,81.9 46.99,81.9 TPX154.1
MCASP1_AXR5/UART8_RXD: length 40.7
  TOP w0.191: U9.Y24 v1(91.05,76.15)
  L5-PWR/GND w0.097: TPX181.1 53.09,75.81 59.82,75.81 60.58,75.05 73.79,75.05 74.55,74.28 84.45,74.28 85.93,75.76 90.5,75.76 90.89,76.15 v1(91.05,76.15)
MCASP1_AXR6/UART8_TXD: length 42
  TOP w0.191: U9.AA25 90.65,76.55 v1(90.25,76.95)
  L7-SIGNAL w0.097: TPX10.1 50.43,77.98 54.47,77.98 54.86,77.59 85.98,77.59 86.51,78.12 88.8,78.12 89.02,77.9 89.02,77.66 89.3,77.38 89.82,77.38 v1(90.25,76.95)
MCASP1_AXR7/PRG0_RGMII2_TD0: length 39.1
  TOP w0.191: U9.AG26 89.85,81.35 v1(89.45,81.75)
  L7-SIGNAL w0.097: v1(89.45,81.75) 89.04,82.16 88.45,82.16 88.22,82.4 88.22,82.7 88,82.92 86.49,82.92 85.98,83.43 61.72,83.43 60.58,84.57 53.21,84.57 TPX78.1
MCASP1_AXR8/PRG0_RGMII2_TD1: length 42.7
  TOP w0.191: U9.AF27 89.05,80.55 v1(88.65,80.95)
  L7-SIGNAL w0.097: v1(88.65,80.95) 88.37,80.95 87.95,81.37 86.31,81.37 85.91,80.97 75.74,80.97 74.8,81.9 48.01,81.9 TPX79.1
MCASP2_ACLKX/SPI3_D1: length 41.8
  TOP w0.191: U9.AA29 v1(87.05,76.95)
  L7-SIGNAL w0.097: v1(87.05,76.95) 86.67,76.95 86.54,77.08 54.74,77.08 54.53,76.87 46.95,76.87 TPX160.1
MCASP2_AFSX/SPI3_D0: length 39.2
  TOP w0.191: v1(89.45,76.95) 89.85,76.55 U9.AA26
  L7-SIGNAL w0.097: TPX159.1 51.82,77.08 54.1,77.08 54.4,77.38 86.75,77.38 86.78,77.34 89.05,77.34 v1(89.45,76.95)
MCASP2_AXR3/SPI3_CLK: length 40
  TOP w0.191: v1(90.25,76.15) 90.65,75.75 U9.Y25
  L5-PWR/GND w0.097: TPX134.1 51.82,76.82 54.61,76.82 54.86,76.57 89.83,76.57 v1(90.25,76.15)
MCASP6_ACLKR/PRG1_RGMII1_RX_CTL: length 45.5
  TOP w0.191: U9.AH23 92.25,82.15 v1(91.85,82.55)
  BOTTOM w0.127: v1(91.85,82.55) 91.44,82.96 91.44,83.51 91.15,83.81 56.77,83.81 54.99,82.03 49.4,82.03 TPX148.1
MCASP6_ACLKX/PRG1_RGMII1_RD0: length 45.3
  TOP w0.191: v1(91.85,78.55) 92.25,78.15 U9.AC23
  BOTTOM w0.127: v1(91.85,78.55) 91.45,78.94 85.77,78.94 84.07,80.63 57.15,80.63 56.01,79.49 49.4,79.49 TPX74.1
MCASP6_AFSR/PRG1_RGMII1_RXC: length 48
  TOP w0.191: U9.AD22 93.05,78.95 v1(92.65,79.35)
  BOTTOM w0.127: v1(92.65,79.35) 92.25,79.75 85.73,79.75 84.47,81 56.63,81 56.26,80.63 46.74,80.63 TPX124.1
MCASP6_AFSX/PRG1_RGMII1_RD1: length 46.1
  TOP w0.191: U9.AG22 93.05,81.35 v1(92.65,81.75)
  L5-PWR/GND w0.097: v1(92.65,81.75) 92.29,82.11 92.29,83.9 91.49,84.7 56.77,84.7 55.75,85.71 50.55,85.71 TPX98.1
MCASP6_AXR0/PRG1_RGMII1_RD2: length 44.9
  TOP w0.191: v1(92.65,80.95) 93.05,80.55 U9.AF22
  L5-PWR/GND w0.097: TPX149.1 52.06,84.45 90.67,84.45 91.44,83.68 91.44,81.65 91.7,81.39 92.21,81.39 v1(92.65,80.95)
MCU_ADC0_AIN0: length 32.3
  TOP w0.229: v1(90.25,67.35) 90.65,67.75 U9.K25
  L5-PWR/GND w0.097: v1(90.25,67.35) 89.81,66.91 88.5,66.91 88.21,66.62 88.21,66.4 88,66.18 85.5,66.18 83.06,63.74 77.47,63.74 75.52,61.8 63.58,61.8 62.74,60.95 61.98,60.95 TPX43.1
MCU_ADC0_AIN1: length 51.8
  TOP w0.229: v1(89.45,67.35) 89.85,67.75 U9.K26
  L4-SIGNAL w0.097: v1(89.45,67.35) 89.08,66.98 85.66,66.98 83.82,65.14 78.23,65.14 77.66,64.57 72.2,64.57 71.37,65.39 62.1,65.39 61.6,64.89 TPX89.1
MCU_ADC0_AIN2: length 26
  TOP w0.229: v1(87.85,67.35) 88.25,67.75 U9.K28
  BOTTOM w0.127: v1(87.85,67.35) 87.45,66.95 86.65,66.95 83.19,63.49 77.85,63.49 72.39,58.03 67.88,58.03 67.12,57.27 TPX190.1
MCU_ADC0_AIN3: length 24.6
  TOP w0.229: v1(87.85,68.15) 88.25,68.55 U9.L28
  BOTTOM w0.127: v1(87.85,68.15) 87.45,67.75 86.81,67.75 82.93,63.87 77.6,63.87 72.9,59.17 68.45,59.17 TPX114.1
MCU_ADC0_AIN4: length 31.2
  TOP w0.229: v1(91.05,67.35) 91.45,67.75 U9.K24
  L5-PWR/GND w0.097: TPX42.1 64.91,61.34 75.83,61.34 77.81,63.32 83.9,63.32 85.17,64.59 88.8,64.59 89.01,64.8 89.01,64.99 89.09,65.08 89.09,65.09 89.3,65.3 89.32,65.3 89.4,65.39 89.6,65.39 89.81,65.6 89.81,65.79 89.81,65.8 89.81,66.62 90.1,66.91 90.61,66.91 v1(91.05,67.35)
MCU_ADC0_AIN5: length 18.4
  TOP w0.229: v1(88.65,67.35) 89.05,67.75 U9.K27
  L5-PWR/GND w0.097: v1(88.65,67.35) 88.29,66.99 85.41,66.99 83.31,64.89 81.91,64.89 81.24,64.21 76.66,64.21 75.44,62.98 73.53,62.98 TPX167.1
MCU_ADC0_AIN6: length 18.1
  TOP w0.229: v1(87.05,67.35) 87.05,67.35 U9.K29
  L5-PWR/GND w0.097: TPX115.1 72.52,63.24 75.18,63.24 76.37,64.42 81.07,64.42 81.75,65.1 83.22,65.1 85.47,67.35 v1(87.05,67.35)
MCU_ADC0_AIN7: length 20.9
  TOP w0.229: v1(87.05,68.15) 87.05,68.15 U9.L29
  L5-PWR/GND w0.097: TPX140.1 70.61,63.87 74.68,63.87 75.69,64.89 80.94,64.89 81.57,65.52 83.05,65.52 85.68,68.15 v1(87.05,68.15)
MCU_ADC1_AIN0: length 31.9
  TOP w0.229: v1(91.85,69.75) 91.85,69.75 U9.N23
  L9-SIGNAL w0.097: TPX66.1 66.17,59.43 73.79,59.43 82.91,68.55 89.39,68.55 89.42,68.58 89.6,68.58 89.81,68.79 89.81,68.98 89.88,69.04 89.88,69.1 90.1,69.31 90.15,69.31 90.15,69.31 91.42,69.31 v1(91.85,69.75)
MCU_ADC1_AIN1: length 36.8
  TOP w0.229: U9.M25 90.25,68.95 v1(90.25,68.95)
  L9-SIGNAL w0.097: TPX69.1 63.31,54.03 70.3,54.03 82.44,66.18 85.62,66.18 86.42,66.98 88,66.98 88.28,67.26 88.28,67.5 88.32,67.53 88.32,67.53 88.5,67.71 89.57,67.71 89.88,68.03 89.88,68.58 v1(90.25,68.95)
MCU_ADC1_AIN2: length 56.8
  TOP w0.229: U9.L24 91.05,68.15 v1(91.05,68.15)
  L4-SIGNAL w0.097: v1(91.05,68.15) 90.68,68.51 86.17,68.51 83.44,65.78 78.23,65.78 77.22,66.79 67.06,66.79 66.55,66.28 38.73,66.28 TPX38.1
MCU_ADC1_AIN3: length 22.1
  TOP w0.229: U9.L26 89.45,68.15 v1(89.45,68.15)
  L5-PWR/GND w0.097: v1(89.45,68.15) 89.09,67.79 85.62,67.79 83.14,65.31 81.66,65.31 80.98,64.63 76.2,64.63 75.06,63.49 71.5,63.49 TPX39.1
MCU_ADC1_AIN4: length 30.1
  TOP w0.229: U9.N24 91.05,69.75 v1(91.05,69.75)
  BOTTOM w0.127: TPX139.1 67.69,59.68 72.64,59.68 78.23,65.27 83.31,65.27 86.11,68.06 86.11,68.7 86.76,69.35 90.65,69.35 v1(91.05,69.75)
MCU_ADC1_AIN5: length 36.4
  TOP w0.229: v1(91.05,68.95) 91.45,69.35 U9.M24
  L9-SIGNAL w0.097: TPX90.1 64.26,53.71 70.48,53.71 82.55,65.78 85.52,65.78 85.85,66.11 87.93,66.11 88.21,66.39 88.21,66.63 88.5,66.91 89.27,66.91 89.34,66.98 89.6,66.98 89.82,67.2 89.82,67.45 90.14,67.78 90.4,67.78 90.61,67.99 90.61,68.51 v1(91.05,68.95)
MCU_ADC1_AIN6: length 53.9
  TOP w0.229: v1(90.25,68.15) 90.65,68.55 U9.L25
  L4-SIGNAL w0.097: v1(90.25,68.15) 89.88,67.78 85.95,67.78 83.57,65.39 78.23,65.39 77.91,65.72 76.14,65.72 76,65.58 72.08,65.58 71.94,65.72 61.92,65.72 61.72,65.52 39.24,65.52 TPX65.1
MCU_ADC1_AIN7: length 35.6
  TOP w0.229: U9.L27 89.05,68.55 v1(88.65,68.15)
  L9-SIGNAL w0.097: TPX117.1 62.36,54.35 70.1,54.35 82.37,66.61 85.55,66.61 86.66,67.73 88.23,67.73 v1(88.65,68.15)
MCU_ADC_EXT_TRIGGER0: length 31.1
  TOP w0.229: v1(89.45,65.75) 89.85,66.15 U9.H26
  L7-SIGNAL w0.097: TPX14.1 63.25,57.77 74.68,57.77 81.81,64.91 85.11,64.91 86.32,66.11 89.08,66.11 v1(89.45,65.75)
MCU_ADC_EXT_TRIGGER1: length 30.8
  TOP w0.229: U9.H27 88.65,65.75 v1(88.65,65.75)
  L9-SIGNAL w0.097: v1(88.65,65.75) 88.37,65.75 88,65.38 84.08,65.38 80.86,62.16 79.44,62.16 70.61,53.33 65.15,53.33 TPX118.1
MCU_CAN0_STBZ: length 48.6
  TOP w0.229: v1(87.85,63.35) 88.25,63.75 U9.E28
  L4-SIGNAL w0.097: v1(44.2,63.36) 45.72,63.36 46.48,62.6 56.9,62.6 58.16,61.33 59.18,61.33 60.83,62.98 87.48,62.98 v1(87.85,63.35)
  BOTTOM w0.229: R2102.1 42.54,34.46 42.67,34.58 v1(42.67,35.04)
MCU_CAN1_STB: length 49
  TOP w0.229: v1(87.85,64.15) 87.85,64.15 U9.F28
  L4-SIGNAL w0.097: TPX324.1 40.16,63.9 43.4,63.9 43.43,63.87 78.65,63.87 78.95,63.57 86.74,63.57 86.75,63.57 86.96,63.78 87.48,63.78 v1(87.85,64.15)
MCU_HYPERBUS0_CS1#: length 21.6
  TOP w0.229: U9.E22 93.05,63.75 v1(92.65,63.35)
  L9-SIGNAL w0.097: v1(92.65,63.35) 92.38,63.08 92.38,62.86 92.3,62.78 92.3,62.71 92.28,62.7 92.28,62.39 92.3,62.38 92.3,61.91 92.28,61.9 92.28,61.59 92.3,61.58 92.3,61.11 92.28,61.1 92.28,60.79 92.3,60.78 92.3,60.31 92.28,60.3 92.28,59.99 92.3,59.98 92.3,58.63 90.68,57.01 86.74,57.01 v1(80.26,50.54)
  BOTTOM w0.229: R3137.1 v1(80.26,50.54)
MCU_HYPERBUS0_RESET#: length 19.4
  TOP w0.229: v1(95.05,63.35) 95.45,63.75 U9.E19
  L2-SIGNAL w0.097: v1(95.05,63.35) 94.61,62.91 94.1,62.91 93.88,62.7 93.88,61.59 93.6,61.31 93.3,61.31 93.08,61.1 93.08,60.79 92.8,60.51 92.5,60.51 92.28,60.3 92.28,59.76 91.57,59.05 91.57,52.44 90.68,51.55 90.04,51.55 87.27,48.77
MCU_HYPERBUS0_RESETO#: length 1.1
  TOP w0.229: R3136.1 R138.2
MCU_I2C0_SCL: length 190
  TOP w0.229: v1(129.57,92.68) U27.32 ; v1(89.45,66.55) 89.45,66.55 U9.J26 ; R74.2 v1(71.12,58.54)
  L2-SIGNAL w0.097: v1(129.57,92.68) 129.57,85.31 133.35,81.52 134.49,81.52 137.8,78.22 137.8,74.03 138.18,73.65 v1(138.18,30.72)
  L4-SIGNAL w0.097: v1(71.12,58.54) 72.01,57.65 72.01,52.69 67.06,47.74 67.06,37.33 73.96,30.43 92.67,30.43 93.47,31.23 103.89,31.23 104.25,31.59 105.57,31.59 106.56,30.6 109.23,30.6 110.27,31.63 110.71,31.63 111.24,31.1 113.41,31.1 114.43,30.09 119.76,30.09 120.4,30.72 v1(138.18,30.72)
  L7-SIGNAL w0.097: v1(71.12,58.54) 74.8,58.54 82.04,65.78 84.96,65.78 86.13,66.94 89.05,66.94 v1(89.45,66.55)
MCU_I2C0_SDA: length 195
  TOP w0.229: v1(90.25,65.75) 90.25,65.75 U9.H25 ; v1(130.07,94.22) U27.33 ; v1(71.12,60.44) R106.2
  L2-SIGNAL w0.097: v1(138.05,29.96) 138.55,30.47 138.55,73.78 138.12,74.22 138.12,78.66 132.21,84.57 131.06,84.57 130.07,85.57 v1(130.07,94.22) ; v1(71.12,60.44) 79.37,60.44 81.91,62.98 83.57,62.98 85.9,65.31 89.81,65.31 v1(90.25,65.75)
  L4-SIGNAL w0.097: 92.86,29.98 93.15,30.27 101.53,30.27 101.86,30.61 106.07,30.61 107.35,29.33 112.27,29.33 112.41,29.46 119.64,29.46 120.68,30.5 137.51,30.5 v1(138.05,29.96) ; v1(71.12,60.44) 71.12,59.55 70.61,59.05 70.61,58.51 71.74,57.38 71.74,54.33 65.71,48.3
  L4-SIGNAL w0.114: 65.71,48.3 65.71,37.66 73.38,29.98 83.64,29.98 83.65,29.99 84.75,29.99 84.76,29.98 92.86,29.98
MCU_I3C0_SCL: length 33.8
  TOP w0.229: v1(89.45,62.55) 89.85,62.95 U9.D26
  L9-SIGNAL w0.097: v1(89.45,62.55) 89.28,62.55 88.84,62.11 88.5,62.11 88.21,61.83 88.21,61.59 87.95,61.33 84.84,61.33 74.67,51.16 71.47,51.16 71.46,51.17 62.36,51.17 TPX70.1
MCU_I3C0_SDA: length 33.5
  TOP w0.229: v1(90.25,62.55) 90.26,62.55 U9.D25
  L9-SIGNAL w0.097: v1(90.25,62.55) 90.04,62.55 89.6,62.11 89.3,62.11 89.01,61.83 89.01,61.59 88.8,61.38 88.5,61.38 88.21,61.1 88.21,60.79 88,60.58 84.67,60.58 75.01,50.92 63.37,50.92 TPX94.1
MCU_I3C0_SDAPULLEN: length 29.2
  TOP w0.229: U9.E26 89.85,63.75 v1(89.45,63.35)
  L7-SIGNAL w0.097: TPX116.1 64.77,56.5 79.76,56.5 86.23,62.98 88.8,62.98 89.17,63.35 v1(89.45,63.35)
MCU_MCAN0_EN: length 59.8
  TOP w0.229: U9.F26 89.85,64.55 v1(89.45,64.15)
  L2-SIGNAL w0.097: v1(89.45,64.15) 89.08,63.78 88.5,63.78 88.21,63.5 88.21,63.19 88,62.98 85.72,62.98 78.1,55.36 55.75,55.36 55.12,54.73 54.29,54.73 53.73,54.17 35.51,54.17 TPX259.1
MCU_MCAN0_RX: length 45.9
  TOP w0.229: v1(87.05,61.75) 87.05,61.75 U9.C29
  L4-SIGNAL w0.097: v1(43.81,61.33) 44.2,60.95 54.48,60.95 54.96,60.47 59.66,60.47 60.77,61.58 79.06,61.58 79.59,61.05 83.8,61.05 84.49,61.75 v1(87.05,61.75)
  BOTTOM w0.229: R2109.1 v1(37.46,33.77)
MCU_MCAN0_TX: length 46.1
  TOP w0.229: v1(87.05,62.55) 87.45,62.95 U9.D29
  L4-SIGNAL w0.097: v1(87.05,62.55) 85.02,62.55 84.81,62.75 61.24,62.75 59.56,61.08 57.98,61.08 57.09,61.97 55.94,61.97 55.79,62.12 55.46,62.12 55.31,61.97 45.97,61.97 45.34,62.6 v1(43.81,62.6)
  BOTTOM w0.229: R2110.1 v1(42.04,34.53)
MCU_MCAN1_RX: length 35.6
  TOP w0.229: v1(91.05,64.95) 91.45,65.35 U9.G24
  L7-SIGNAL w0.097: TPX44.1 63.09,55.64 79.4,55.64 85.87,62.11 89.54,62.11 89.87,62.44 89.87,63.48 90.16,63.78 90.4,63.78 90.62,63.99 90.62,64.26 90.88,64.53 90.88,64.78 v1(91.05,64.95)
MCU_MCAN1_TX: length 29.4
  TOP w0.229: v1(90.25,64.95) 90.25,64.95 U9.G25
  L7-SIGNAL w0.097: TPX15.1 65.79,56.76 79.5,56.76 86.52,63.78 89.6,63.78 89.82,63.99 89.82,64.51 v1(90.25,64.95)
MCU_MDIO0_MDC: length 36.6
  TOP w0.229: v1(91.85,64.15) 92.25,64.55 U9.F23
  L9-SIGNAL w0.097: v1(91.85,64.15) 92.22,63.78 92.22,63.19 91.94,62.91 91.24,62.91 91.24,62.91 90.9,62.91 90.68,62.7 90.68,62.35 90.51,62.18 90.15,62.18 89.84,61.86 89.84,59.86 89.53,59.55 84.71,59.55 75.83,50.67 64.4,50.67 TPX137.1
MCU_MDIO0_MDIO: length 38.3
  TOP w0.229: v1(91.85,63.35) 92.25,63.75 U9.E23
  L9-SIGNAL w0.097: v1(91.85,63.35) 91.48,63.71 90.9,63.71 90.68,63.5 90.68,63.24 90.42,62.98 88.5,62.98 88.22,62.7 88.22,62.39 88,62.18 84.44,62.18 74.57,52.31 69.22,52.31 68.45,51.55 61.47,51.55 TPX13.1
MCU_OSPI0_CLK: length 25.4
  L9-SIGNAL w0.097: v1(83.92,46.95) 84.2,47.23 84.2,47.3 85.79,48.88 90.81,48.88 93.35,51.43 93.35,57.26 93.22,57.39 92.07,57.39 91.82,57.14 91.82,56.45 v1(92.38,55.89)
  BOTTOM w0.229: U24.B2 80.75,46.46 82.11,46.46 82.61,46.97 R253.1 83.3,46.95 v1(83.92,46.95) ; v1(92.38,55.89) 92.61,55.89 93.06,55.44 R247.2
MCU_OSPI0_CS0#: length 32.4
  TOP w0.229: R153.1 81.36,46.07 ; 81.36,46.07 81.41,46.12 ; 81.36,46.07 v1(80.75,45.46) ; v1(95.05,64.15) 95.05,64.15 U9.F19
  L2-SIGNAL w0.097: v1(95.05,64.15) 95.42,63.78 95.42,63.02 95.31,62.91 94.9,62.91 94.68,62.7 94.68,62.29 94.61,62.22 94.61,61.59 94.4,61.38 93.95,61.38 93.81,61.24 93.81,60.79 93.6,60.58 93.36,60.58 93.08,60.31 93.08,59.8 91.95,58.66 91.95,50.79 89.53,48.38 86.74,48.38 85.72,47.36 85.72,46.09 85.09,45.46 82.31,45.46 81.92,45.06 81.15,45.06 v1(80.75,45.46)
  BOTTOM w0.229: U24.C2 v1(80.75,45.46)
MCU_OSPI0_D0: length 32.1
  TOP w0.229: v1(94.25,62.55) 94.65,62.95 U9.D20 ; R154.2 80.93,42.68 80.58,43.02 80.52,43.02 80.21,43.32 80.21,44 v1(79.75,44.46)
  L7-SIGNAL w0.097: v1(79.75,44.46) 80.13,44.84 80.9,44.84 81.18,44.57 84.71,44.57 88.27,48.12 90.04,48.12 93.34,51.42 93.34,58.16 94.62,59.43 94.62,62.18 v1(94.25,62.55)
  BOTTOM w0.229: U24.D3 v1(79.75,44.46)
MCU_OSPI0_D1: length 34.4
  TOP w0.229: R149.2 82.38,45.19 81.66,44.46 v1(80.75,44.46) ; v1(95.05,64.95) 95.05,64.95 U9.G19
  L9-SIGNAL w0.097: v1(95.05,64.95) 94.61,64.51 94.1,64.51 93.81,64.23 93.81,63.19 93.53,62.91 93.3,62.91 93.01,62.63 93.01,61.9 93.02,61.9 93.02,61.59 93.01,58.11 93.73,57.39 93.73,51.04 91.06,48.38 88.39,48.38 84.48,44.46 v1(80.75,44.46)
  BOTTOM w0.229: U24.D2 v1(80.75,44.46)
